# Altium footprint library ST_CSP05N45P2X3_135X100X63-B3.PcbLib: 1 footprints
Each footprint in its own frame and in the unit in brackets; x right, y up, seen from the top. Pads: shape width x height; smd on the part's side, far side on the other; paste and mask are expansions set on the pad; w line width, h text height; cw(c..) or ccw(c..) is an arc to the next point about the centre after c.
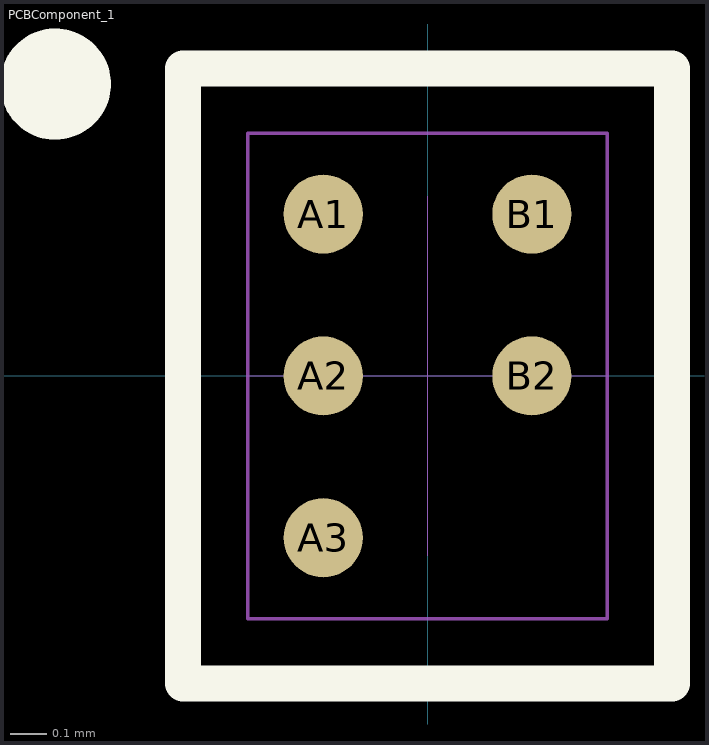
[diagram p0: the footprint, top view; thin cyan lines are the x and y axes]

## PCBComponent_1 [mm]
pads (5):
  round 0.22 smd paste-20 mask+0.05: A1(-0.29,0.45) A2(-0.29,0) A3(-0.29,-0.45) B1(0.29,0.45) B2(0.29,0)
Top Overlay:
  circle w0.2: c-1.035,0.811 r0.054
  lines w0.1: -0.68,-0.855 -0.68,0.855 0.68,0.855 0.68,-0.855 -0.68,-0.855
Top Paste:
  rectangle: -0.4,-0.56 -0.18,-0.34
  rectangle: -0.4,-0.11 -0.18,0.11
  rectangle: 0.18,-0.11 0.4,0.11
  rectangle: 0.18,0.34 0.4,0.56
  rectangle: -0.4,0.34 -0.18,0.56
Mechanical 15:
  lines w0.001: -0.5,0 0.5,0 ; 0,-0.5 0,0.5
  lines w0.01: -0.5,-0.675 -0.5,0.675 0.5,0.675 0.5,-0.675 -0.5,-0.675
3D body: height 0.63, standoff 0.26, extent -0.5,-0.675 0.5,0.675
